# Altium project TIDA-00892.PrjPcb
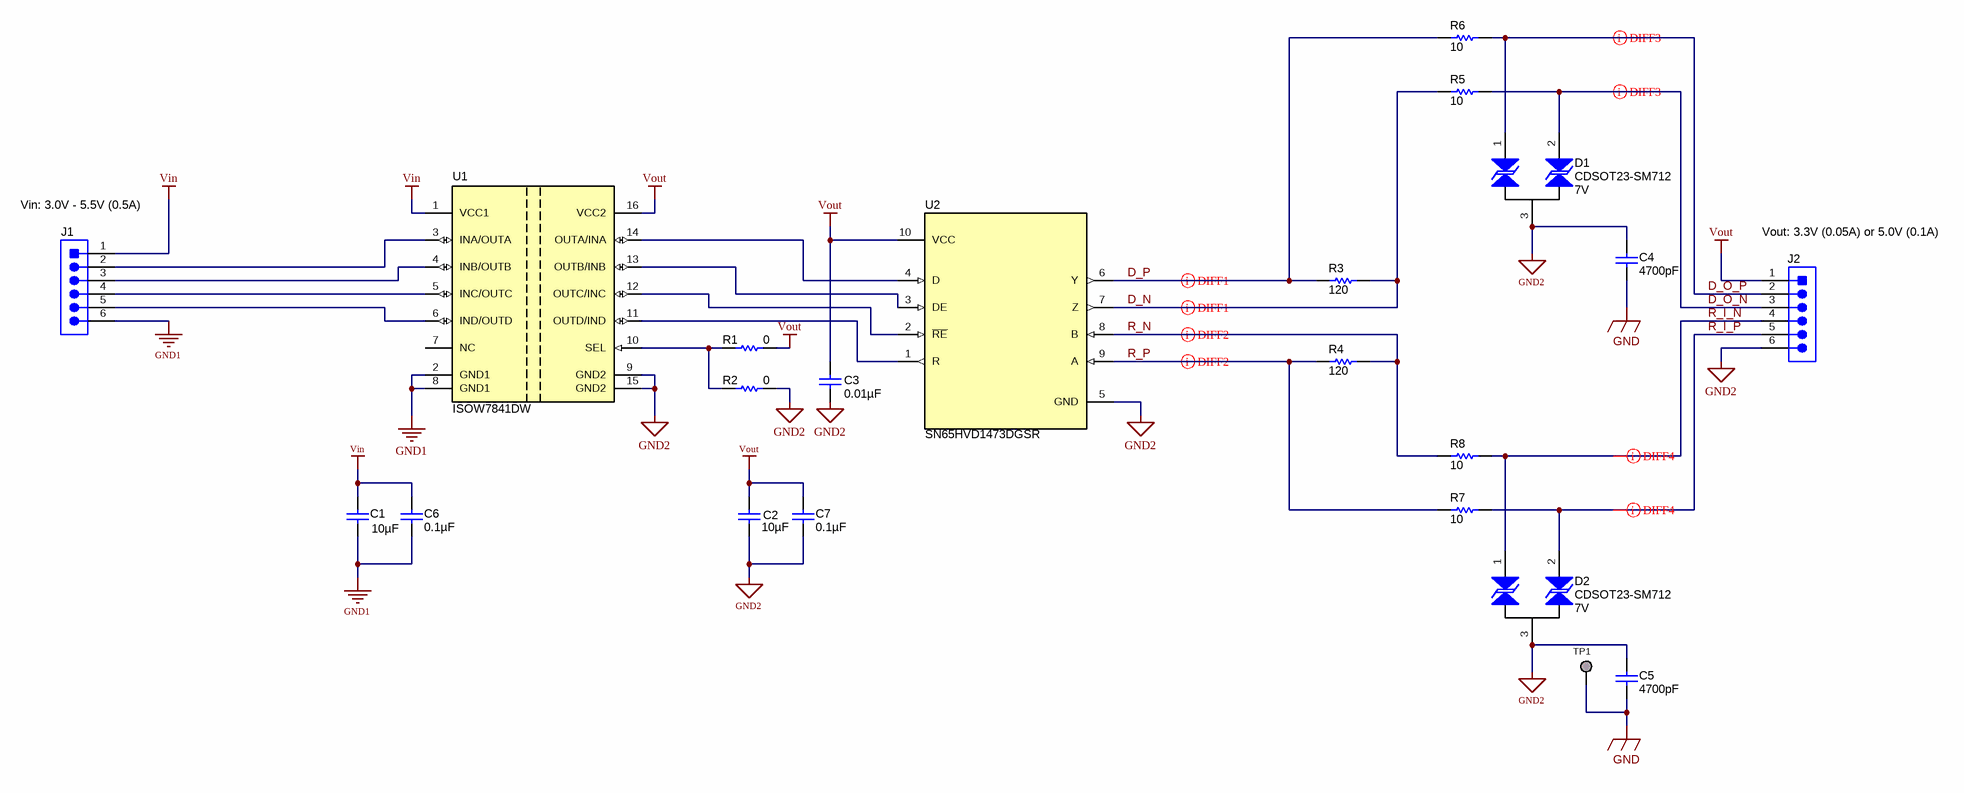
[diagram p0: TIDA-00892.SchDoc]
CopyrightYear: 2015; EVM_Orderable: N/A; PCB_Layout: Tessolve; PCB_Rev: A; PRJ_Customer: Public Release; PRJ_Engineer: Anand Reghunathan; PRJ_Number: TIDA-00892; PRJ_Title: TIDA-00892; SCH_Rev: A; TechSupport: http://www.ti.com/support; TID: TIDA-00892
2 sheets, 27 parts. Net scope: global (net labels, ports and power ports of the same name join across sheets).
Board file: TIDA-00892.PcbDoc
Sheets:
  TIDA-00892.SchDoc
  TIDA-00892_Hardware.SchDoc

## Sheet TIDA-00892.SchDoc
size 431 x 279 mm; Date: Not shown in title block; ApprovedBy: Not shown in title block; CheckedBy: Not shown in title block; Author: Not shown in title block; CompanyName: Not shown in title block; Engineer: Not shown in title block; Organization: Not shown in title block; Address1: Not shown in title block; Address2: Not shown in title block; Address3: Not shown in title block; Address4: Not shown in title block; DocumentNumber: 1; Revision: Use project parameter SCH_Rev; SheetNumber: 2; SheetTotal: 3; PageSetup: Record=PageOptions¦CenterHorizontal=True¦CenterVertical=True¦PrintScale=1.00¦XCorrection=1.00¦YCorrection=1.00¦PrintKind=0¦BorderSize=5000000¦LeftOffset=0¦BottomOffset=0¦Orientation=2¦PaperLength=1000¦PaperWidth=1000¦Scale=100¦PaperSource=15¦PrintQuality=600¦MediaType=1¦DitherType=10¦PaperKind=Letter¦PrintScaleMode=1

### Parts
C1  ValueDisplayed: 10µF  [0805_HV]  (hidden comment: GRM21BR6YA106KE43L)
C2  ValueDisplayed: 10µF  [0805_HV]  (hidden comment: GRM21BR6YA106KE43L)
C3  ValueDisplayed: 0.01µF  [0603]  (hidden comment: GCM188R71H103KA37D)
C4  ValueDisplayed: 4700pF  [1210]  (hidden comment: 202S41W472KV4E)
C5  ValueDisplayed: 4700pF  [1210]  (hidden comment: 202S41W472KV4E)
C6  ValueDisplayed: 0.1µF  [0402]  (hidden comment: GRM155R71E104KE14D)
C7  ValueDisplayed: 0.1µF  [0402]  (hidden comment: GRM155R71E104KE14D)
D1  CDSOT23-SM712  value 7V  [SOT-23]
D2  CDSOT23-SM712  value 7V  [SOT-23]
J1  Vin: 3.0V - 5.5V (0.5A)  [Harwin_M22-25106]  (hidden comment: M22-2510605)
J2  Vout: 3.3V (0.05A) or 5.0V (0.1A)  [Harwin_M22-25106]  (hidden comment: M22-2510605)
R1  ValueDisplayed: 0  [0201M]  (hidden comment: ERJ-1GE0R00C)
R2  ValueDisplayed: 0  [0201M]  (hidden comment: ERJ-1GE0R00C)
R3  ValueDisplayed: 120  [0805_HV]  (hidden comment: ESR10EZPF1200)
R4  ValueDisplayed: 120  [0805_HV]  (hidden comment: ESR10EZPF1200)
R5  ValueDisplayed: 10  [0603]  (hidden comment: CRCW060310R0JNEAHP)
R6  ValueDisplayed: 10  [0603]  (hidden comment: CRCW060310R0JNEAHP)
R7  ValueDisplayed: 10  [0603]  (hidden comment: CRCW060310R0JNEAHP)
R8  ValueDisplayed: 10  [0603]  (hidden comment: CRCW060310R0JNEAHP)
TP1  TESTPOINT  [Keystone_5019]  (value not drawn)
U1  ISOW7841DW  [DW0016B_N]
U2  SN65HVD1473DGSR  [DGS0010A_N]

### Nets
GND: C4.2 C5.2 TP1.1
GND1: C1.2 C6.2 J1.6 U1.2(GND1) U1.8(GND1)
GND2: C2.2 C3.2 C4.1 C5.1 C7.2 D1.3 D2.3 J2.6 R2.2 U1.9(GND2) U1.15(GND2) U2.5(GND)
Vin: C1.1 C6.1 J1.1 U1.1(VCC1)
Vout: C2.1 C3.1 C7.1 J2.1 R1.2 U1.16(VCC2) U2.10(VCC)
D_N: R3.2 R5.1 U2.7(Z)
D_O_N: D1.2 J2.3 R5.2
D_O_P: D1.1 J2.2 R6.2
D_P: R3.1 R6.1 U2.6(Y)
R_I_N: D2.1 J2.4 R8.2
R_I_P: D2.2 J2.5 R7.2
R_N: R4.1 R8.1 U2.8(B)
R_P: R4.2 R7.1 U2.9(A)
NetJ1_2: J1.2 U1.3(INA/OUTA)
NetJ1_3: J1.3 U1.4(INB/OUTB)
NetJ1_4: J1.4 U1.5(INC/OUTC)
NetJ1_5: J1.5 U1.6(IND/OUTD)
NetR1_1: R1.1 R2.1 U1.10(SEL)
NetU1_11: U1.11(OUTD/IND) U2.1(R)
NetU1_12: U1.12(OUTC/INC) U2.2(~{RE})
NetU1_13: U1.13(OUTB/INB) U2.3(DE)
NetU1_14: U1.14(OUTA/INA) U2.4(D)

Not connected (* = marked no-connect by the designer): U1 7(NC)

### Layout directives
differential pair: D_N, D_O_N, D_O_P, D_P, R_I_N, R_I_P, R_N, R_P

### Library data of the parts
C1 C2 = GRM21BR6YA106KE43L: CAP, CERM, 10 µF, 35 V, +/- 10%, X5R, 0805; Manufacturer: MuRata; Polarized: N; CompType: Capacitor; Value: 10uF; U/M: EA; Cap_F: 0.00001; Tolerance_%: 10; Value1: Unknown; VDC_V: 35; Value2: 35V; TaMin_C: -55; TaMax_C: 85; Cap_Case: 0805
C3 = GCM188R71H103KA37D: CAP, CERM, 0.01 µF, 50 V, +/- 10%, X7R, AEC-Q200 Grade 1, 0603; Manufacturer: MuRata; Polarized: N; CompType: Capacitor; Value: 0.01uF; U/M: EA; Cap_F: 0.00000001; Tolerance_%: 10; Value1: Unknown; VDC_V: 50; Value2: 50V; TaMin_C: -55; TaMax_C: 125; AEC Category: Q200; AEC Qualified: Y; AEC Grade: 1
C4 C5 = 202S41W472KV4E: CAP, CERM, 4700 pF, 2000 V, +/- 10%, X7R, 1210; Manufacturer: Johanson Technology; Polarized: N; CompType: Capacitor; Value: 4700pF; U/M: EA; Cap_F: 0.0000000047; Tolerance_%: 10; Value1: Unknown; VDC_V: 2000; Value2: 2000V; TaMin_C: -55; TaMax_C: 125; AEC Category: Q200
C6 C7 = GRM155R71E104KE14D: CAP, CERM, 0.1 µF, 25 V, +/- 10%, X7R, 0402; Manufacturer: MuRata; Polarized: N; CompType: Capacitor; Value: 0.1uF; U/M: EA; Cap_F: 0.0000001; Tolerance_%: 10; Value1: Unknown; VDC_V: 25; Value2: 25V; TaMin_C: -55; TaMax_C: 125; AEC Category: Q200
D1 D2 = CDSOT23-SM712: Diode, TVS, Bi, 7 V, 400 W, SOT-23; Manufacturer: Bourns; SymbolCreator: a0411947; U/M: EA; Power_W: 400; Vr_V: 7; Value1: 400W; AEC Category: Q101
J1 J2 = M22-2510605: Header, 2mm, 6x1, Gold, TH; Manufacturer: Harwin; SymbolCreator: a0412235; Pitch_mm: 2; Gender: Male; Shrouded: N; Row_Count: 1; Voltage_V: 500
R1 R2 = ERJ-1GE0R00C: RES, 0, 5%, 0.05 W, 0201; Manufacturer: Panasonic; CompType: Resistor; Value: 0; Value_Code: 0000; Tolerance_%: 5; Power_W: 0.05; Value2: 0.05W; VDC_V: 15; TempCo: 600 ppm/C; SizeArea_mm2: 0.18; SizeAreaWB_mm2: 2.08; SizeX_mm: 0.6; SizeY_mm: 0.3; SizeZ_mm: 0.26; EIA_Code: E24; U/M: EA; AEC Category: Q200
R3 R4 = ESR10EZPF1200: RES, 120, 1%, 0.4 W, 0805; Manufacturer: Rohm; CompType: Resistor; Value: 120; Value_Code: 120R; Tolerance_%: 1; Power_W: 0.4; Value2: 0.4W; VDC_V: 150; TempCo: 100 ppm/C; U/M: EA; AEC Category: Q200
R5-R8 = CRCW060310R0JNEAHP: RES, 10, 5%, 0.25 W, 0603; Manufacturer: Vishay-Dale; CompType: Resistor; Value: 10; Value_Code: 10R0; Tolerance_%: 5; Power_W: 0.25; Value2: 0.25W; VDC_V: 75; TempCo: 200 ppm/C; EIA_Code: E24; U/M: EA; AEC Category: Q200
TP1 = 5019: Test Point, Miniature, SMT; Manufacturer: Keystone; CompType: Test Point Loop; U/M: EA
U1 = ISOW7841DWR: ISOW7841DW, DW0016B; Manufacturer: Texas Instruments; SymbolCreator: a0411947; SizeArea_mm2: 107.12; SizeAreaWB_mm2: 152.52; SizeX_mm: 10.4; SizeY_mm: 10.3; SizeZ_mm: 2.65; CompType: IC; U/M: EA
U2 = SN65HVD1473DGSR: 3.3-V Full-Duplex RS-485 Transceiver With +/-16-kV IEC ESD, DGS0010A; Manufacturer: Texas Instruments; SymbolCreator: a0411947; CompType: IC; U/M: EA

## Sheet TIDA-00892_Hardware.SchDoc: Hardware Sheet
size 431 x 279 mm; Date: Not shown in title block; ApprovedBy: Not shown in title block; CheckedBy: Not shown in title block; Author: Not shown in title block; CompanyName: Not shown in title block; Engineer: Not shown in title block; Organization: Not shown in title block; Address1: Not shown in title block; Address2: Not shown in title block; Address3: Not shown in title block; Address4: Not shown in title block; DocumentNumber: 1; Revision: Use project parameter SCH_Rev; SheetNumber: 3; SheetTotal: 3; PageSetup: Record=PageOptions¦CenterHorizontal=True¦CenterVertical=True¦PrintScale=1.00¦XCorrection=1.00¦YCorrection=1.00¦PrintKind=0¦BorderSize=5000000¦LeftOffset=0¦BottomOffset=0¦Orientation=2¦PaperLength=1000¦PaperWidth=1000¦Scale=100¦PaperSource=15¦PrintQuality=600¦MediaType=1¦DitherType=10¦PaperKind=Letter¦PrintScaleMode=1
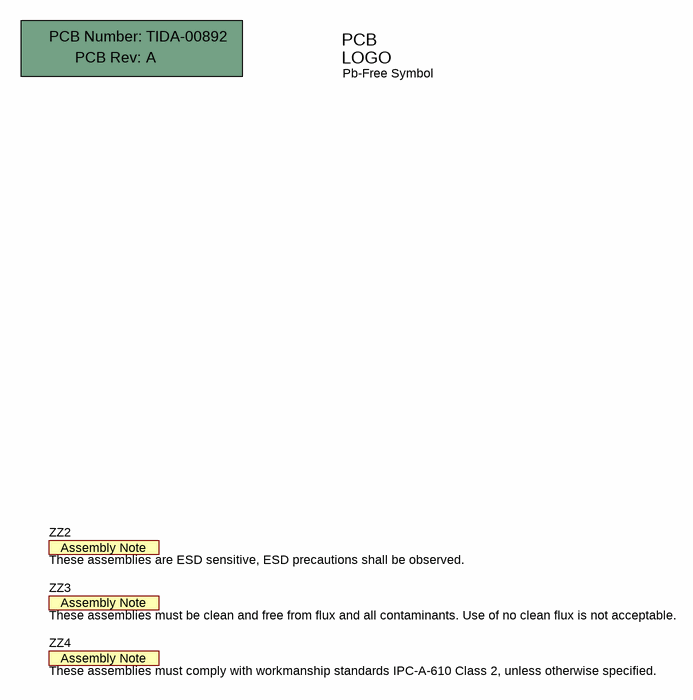
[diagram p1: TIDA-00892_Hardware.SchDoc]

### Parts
!PCB  Printed Circuit Board  (value not drawn)  (mechanical)
Logo1  Pb-Free Symbol  [Pb-Free_Overlay_Small]  (no BOM)
ZZ2  These assemblies are ESD sensitive, ESD precautions shall be observed.  [AssemblyNote]  (no BOM)
ZZ3  These assemblies must be clean and free from flux and all contaminants. Use of no clean flux is not acceptable.  [AssemblyNote]  (no BOM)
ZZ4  These assemblies must comply with workmanship standards IPC-A-610 Class 2, unless otherwise specified.  [AssemblyNote]  (no BOM)

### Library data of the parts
!PCB = PCB: Manufacturer: Any; PartNumber: TIDA-00892; SymbolCreator: a0412235
Logo1 = Pb-Free: SymbolCreator: a0412235
ZZ2-ZZ4 = AssemblyNote: SymbolCreator: codlsc

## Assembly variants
001: not fitted R1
